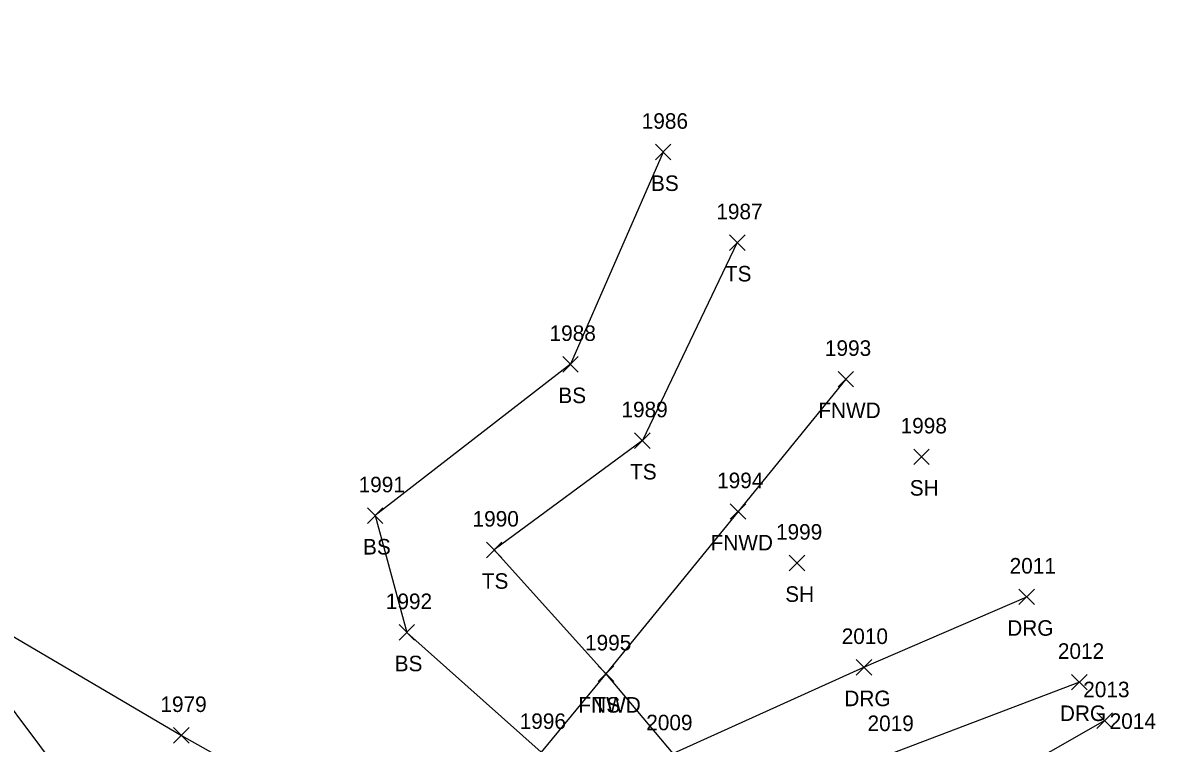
# Model space of a CAD drawing. Extents: x 1501299 to 1502485, y 381423 to 383765.
# Drawn here: x 1501597.6 to 1501743.2, y 383405.5 to 383498.2 of the extents above; entities that cross this region are included whole.
import ezdxf

# ---------------------------------------------------------------- set-up
doc = ezdxf.new("R2010")
doc.units = 0
for name, color, linetype in [('L_A', 7, 'Continuous'), ('L_I', 7, 'Continuous'), ('L_TIC', 7, 'Continuous'), ('LAWA', 7, 'Continuous'), ('LELB', 7, 'Continuous'), ('LFNC', 7, 'Continuous'), ('R_A', 7, 'Continuous'), ('R_I', 7, 'Continuous'), ('R_TIC', 7, 'Continuous'), ('RDG', 7, 'Continuous')]:
    doc.layers.add(name, color=color, linetype=linetype)

msp = doc.modelspace()

# ---------------------------------------------------------------- linework, layer by layer
at = {"layer": 'L_TIC'}
for points in [[(1501678.96, 383480.54), (1501680.96, 383482.54)], [(1501680.96, 383480.54), (1501678.96, 383482.54)], [(1501688.5, 383468.9), (1501690.5, 383470.9)], [(1501690.5, 383468.9), (1501688.5, 383470.9)], [(1501667.05, 383453.25), (1501669.05, 383455.25)], [(1501669.05, 383453.25), (1501667.05, 383455.25)], [(1501702.45, 383451.33), (1501704.45, 383453.33)], [(1501704.45, 383451.33), (1501702.45, 383453.33)], [(1501676.3, 383443.43), (1501678.3, 383445.43)], [(1501678.3, 383443.43), (1501676.3, 383445.43)], [(1501712.18, 383441.35), (1501714.18, 383443.35)], [(1501714.18, 383441.35), (1501712.18, 383443.35)], [(1501641.94, 383433.78), (1501643.94, 383435.78)], [(1501643.94, 383433.78), (1501641.94, 383435.78)], [(1501688.59, 383434.31), (1501690.59, 383436.31)], [(1501690.59, 383434.31), (1501688.59, 383436.31)], [(1501657.24, 383429.37), (1501659.24, 383431.37)], [(1501659.24, 383429.37), (1501657.24, 383431.37)], [(1501696.17, 383427.69), (1501698.17, 383429.69)], [(1501698.17, 383427.69), (1501696.17, 383429.69)], [(1501646.01, 383418.76), (1501648.01, 383420.76)], [(1501648.01, 383418.76), (1501646.01, 383420.76)], [(1501671.61, 383413.44), (1501673.61, 383415.44)], [(1501673.61, 383413.44), (1501671.61, 383415.44)], [(1501671.61, 383413.44), (1501673.61, 383415.44)], [(1501673.61, 383413.44), (1501671.61, 383415.44)], [(1501735.74, 383407.42), (1501737.74, 383409.42)], [(1501737.74, 383407.42), (1501735.74, 383409.42)], [(1501617.03, 383405.52), (1501619.03, 383407.52)], [(1501619.03, 383405.52), (1501617.03, 383407.52)]]:
    msp.add_lwpolyline(points, dxfattribs=at)
at = {"layer": 'LAWA'}
msp.add_lwpolyline([(1501557.45, 383442.58), (1501587.95, 383421), (1501605.62, 383397.42)], dxfattribs=at)
at = {"layer": 'LELB'}
for points in [[(1501679.96, 383481.54), (1501668.05, 383454.25), (1501642.94, 383434.78), (1501647.01, 383419.76), (1501664.27, 383404.34), (1501660.51, 383391.45)], [(1501689.5, 383469.9), (1501677.3, 383444.43), (1501658.24, 383430.37), (1501672.61, 383414.44), (1501681.22, 383404.17)], [(1501736.74, 383408.42), (1501716.09, 383396.65), (1501697.95, 383387.03), (1501677.93, 383373.61)]]:
    msp.add_lwpolyline(points, dxfattribs=at)
at = {"layer": 'LFNC'}
for points in [[(1501598.42, 383526.97), (1501583.57, 383507.22), (1501582.32, 383503.52), (1501551.42, 383461.96), (1501556.79, 383457.15), (1501570.08, 383443.83), (1501579.66, 383434.51), (1501590.93, 383422.47), (1501618.03, 383406.52), (1501631.82, 383398.73), (1501638.24, 383395.91), (1501648.8, 383391.86), (1501655.59, 383390.21)], [(1501703.45, 383452.33), (1501689.59, 383435.31), (1501672.61, 383414.44), (1501664.27, 383404.34), (1501657.15, 383396.28), (1501655.59, 383390.21)]]:
    msp.add_lwpolyline(points, dxfattribs=at)
at = {"layer": 'R_TIC'}
for points in [[(1501725.71, 383423.33), (1501727.71, 383425.33)], [(1501727.71, 383423.33), (1501725.71, 383425.33)], [(1501704.78, 383414.27), (1501706.78, 383416.27)], [(1501706.78, 383414.27), (1501704.78, 383416.27)], [(1501732.48, 383412.36), (1501734.48, 383414.36)], [(1501734.48, 383412.36), (1501732.48, 383414.36)]]:
    msp.add_lwpolyline(points, dxfattribs=at)
at = {"layer": 'RDG'}
for points in [[(1501585.89, 383364.55), (1501592.45, 383361.85), (1501598.94, 383359.57), (1501609.16, 383359.83), (1501620.56, 383365.39), (1501633.64, 383372.08), (1501645.62, 383382.1), (1501657.1, 383388.25), (1501660.51, 383391.45), (1501681.22, 383404.17), (1501705.78, 383415.27), (1501726.71, 383424.33)], [(1501733.48, 383413.36), (1501709.02, 383404.07), (1501690.81, 383395.36), (1501661.87, 383378.54), (1501644.38, 383366.49), (1501625.85, 383354.69), (1501614.4, 383347.48), (1501609.62, 383341.21), (1501607.04, 383333.42)]]:
    msp.add_lwpolyline(points, dxfattribs=at)

# ---------------------------------------------------------------- texts
at = {"layer": 'L_A'}
for s, p in [('BS', (1501678.4, 383476.54)), ('TS', (1501687.9, 383464.9)), ('BS', (1501666.49, 383449.25)), ('FNWD', (1501699.91, 383447.33)), ('TS', (1501675.71, 383439.43)), ('SH', (1501711.67, 383437.35)), ('BS', (1501641.38, 383429.78)), ('FNWD', (1501686.06, 383430.31)), ('TS', (1501656.65, 383425.37)), ('SH', (1501695.66, 383423.69)), ('BS', (1501645.45, 383414.76)), ('FNWD', (1501669.07, 383409.44)), ('TS', (1501671.02, 383409.44))]:
    msp.add_text(s, height=2, dxfattribs=at).set_placement(p)
at = {"layer": 'L_I'}
for s, p in [('1986', (1501677.21, 383484.54)), ('1987', (1501686.8, 383472.9)), ('1988', (1501665.36, 383457.25)), ('1993', (1501700.76, 383455.33)), ('1989', (1501674.6, 383447.43)), ('1998', (1501710.49, 383445.35)), ('1994', (1501686.9, 383438.31)), ('1991', (1501640.81, 383437.78)), ('1990', (1501655.46, 383433.37)), ('1999', (1501694.47, 383431.69)), ('1992', (1501644.31, 383422.76)), ('1995', (1501669.92, 383417.44)), ('1995', (1501669.92, 383417.44)), ('2013', (1501733.97, 383411.42)), ('1979', (1501615.33, 383409.52)), ('1996', (1501661.52, 383407.34)), ('1996', (1501661.52, 383407.34)), ('2014', (1501737.37, 383407.35)), ('2009', (1501677.79, 383407.17))]:
    msp.add_text(s, height=2, dxfattribs=at).set_placement(p)
at = {"layer": 'R_A'}
for p in [(1501724.2, 383419.33), (1501703.26, 383410.27), (1501730.97, 383408.36)]:
    msp.add_text('DRG', height=2, dxfattribs=at).set_placement(p)
at = {"layer": 'R_I'}
for s, p in [('2011', (1501724.51, 383427.33)), ('2010', (1501702.92, 383418.27)), ('2012', (1501730.71, 383416.36)), ('2009', (1501677.79, 383407.17)), ('2019', (1501706.24, 383407.07))]:
    msp.add_text(s, height=2, dxfattribs=at).set_placement(p)

doc.saveas('drawing.dxf')
